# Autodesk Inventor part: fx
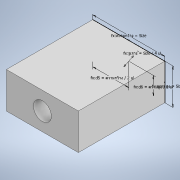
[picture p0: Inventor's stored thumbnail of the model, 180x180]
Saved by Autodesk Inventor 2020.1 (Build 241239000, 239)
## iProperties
Created: 2019-11
Part Number: fx
Material: Generic
Document SubType Name: Modeling
Designer: Synergysoft Dell02
Density: 1 g/cm^3
Appearance: Default
Author: Synergysoft Dell02
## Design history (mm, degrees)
sketch "Sketch1"
  geometry: L1 (0, 0)-(60, 0); L2 (60, 0)-(60, 30); L3 (60, 30)-(0, 30); L4 (0, 30)-(0, 0); C1 r 7.5 at (30, 15); 2 further points
  constraints: 8 end point, 2 midpoint, 2 parallel, 1 centre point, 1 horizontal, 1 horizontal alignment, 1 perpendicular, 1 vertical alignment, 1 other
  dimensions: "d5" = 30 distance from line of C1.centre L4 (derived); "d6" = 15 distance from line of L1 C1.centre (derived)
extrude "Extrusion1" new body sketch "Sketch1" taper "d4" = 0 deg
body "Solid1"
